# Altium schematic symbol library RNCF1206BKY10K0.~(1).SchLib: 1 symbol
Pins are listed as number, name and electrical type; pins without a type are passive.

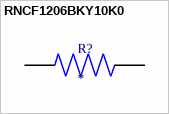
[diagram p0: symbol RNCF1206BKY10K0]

## RNCF1206BKY10K0
designator R?
MP: RNCF1206BKY10K0
footprint RESC3015X65N
pins: 1, 2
